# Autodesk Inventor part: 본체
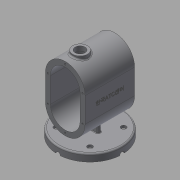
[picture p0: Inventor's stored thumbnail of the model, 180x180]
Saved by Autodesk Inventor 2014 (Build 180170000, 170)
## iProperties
Created: 2016-12
Part Number: 본체
Material: 일반
Document SubType Name: Modeling
Designer: mduedu
Density: 1 g/cm^3
Appearance: 기본값
Author: mduedu
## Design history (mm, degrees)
sketch "스케치1"
  geometry: L1 (40, -25)-(40, 25); L2 (-40, 25)-(-40, -25); L3 (-40, -25)-(40, 25); L4 (40, -25)-(-40, 25); L5 (0, 25)-(0, -25); A1 r 40 centre (0, 25) between (40, 25) and (-40, 25); A2 r 40 centre (0, -25) between (-40, -25) and (40, -25); 1 further point
  constraints: 10 end point, 4 point on circle, 3 tangent, 2 centre point, 2 midpoint, 2 parallel, 1 vertical
  dimensions: "d0" = 130 dimension on A2 A1; "d2" = 80 distance between parallel lines of L1 L2
extrude "돌출1" new body sketch "스케치1" stored distance "d3" = 100; taper "d4" = 0 deg
feature "쉘1" dims "d5" = 10
sketch "스케치2"
  geometry: L1 (-75, 65)-(-90, 65); L2 (-90, 65)-(-90, 0); L3 (-75, 0)-(-75, 65); L4 (-75, 0)-(-90, 0); 1 further point
  constraints: 8 end point, 1 horizontal, 1 horizontal alignment, 1 parallel, 1 perpendicular
  dimensions: "d6" = 90 distance from line of L2 point (0, 0); "d83" = 15 distance of L1.start L1.end; "d84" = 130 diameter of L1 L4
revolve "회전1" sketch "스케치2" stored, may be unused: angle "d85" = 90 deg
fillet "모깎기5" dims "d86" = 3
hole "구멍6" diameter "d89" = 120; stored, may be unused: countersink angle "d93" = 90 deg, drill point angle "d95" = 0 deg; dims "d87" = 10, "d88" = 10, "d90" = 6, "d91" = 4, "d92" = 2, "d94" = 10
sketch "스케치15"
  geometry: L1 (-90, -60)-(-90, 60) reference; C1 r 5 at (-90, 0); 1 further point
  constraints: 1 centre point, 1 horizontal alignment, 1 midpoint
  dimensions: "d96" = 10 diameter of C1
extrude "돌출6" cut sketch "스케치15" stored distance "d97" = 10; taper "d98" = 0 deg
sketch "스케치5"
  geometry: L1 (4, -30)-(-4, -30); L2 (-4, -30)-(-4, 30); L3 (-4, 30)-(4, 30); L4 (4, 30)-(4, -30); L5 (4, -30)-(-4, 30); L6 (-4, -30)-(4, 30); 3 further points
  constraints: 12 end point, 3 midpoint, 2 parallel, 1 coincident, 1 horizontal, 1 perpendicular
  dimensions: "d22" = 8 distance of L2.end L3.end; "d24" = 60 distance of L1.end L2.end
extrude "돌출3" join sketch "스케치5" stored distance "d25" = 80; taper "d26" = 0 deg
feature "면 기울기1" dims angle "d27" = 5 deg
sketch "스케치6"
  geometry: L1 (-18.718, -60.35)-(-20, -75); L2 (-62, -75)-(62, -75) reference; A1 r 40 centre (0, -25) between (-40, -25) and (40, -25) reference; 1 further point
  constraints: 2 end point, 1 point on circle, 1 point on line
  dimensions: "d28" = 20 horizontal distance of A1.centre L1.end; "d102" = 85 deg angle of L2 L1
feature "리브1" sketch "스케치6" dims "d30" = 1, "d31" = 8, "d32" = 0, "d33" = 0, "d34" = 1, "d35" = 1
fillet "모깎기2" dims "d36" = 3
fillet "모깎기3" dims "d37" = 1, "d38" = 1
node "작업 평면1"
sketch "스케치9"
  geometry: 1 further point
sketch "스케치7"
  geometry: L1 (40, 50)-(-40, 50) reference; C1 r 15 at (0, 20); 1 further point
  constraints: 1 centre point, 1 vertical alignment
  dimensions: "d40" = 30 diameter of C1; "d41" = 30 distance from line of C1.centre L1
extrude "돌출4" join sketch "스케치7" stored distance "d42" = 80; taper "d43" = 0 deg
hole "구멍2" diameter "d46" = 20; stored, may be unused: countersink angle "d50" = 90 deg, drill point angle "d52" = 118 deg; dims "d44" = 10, "d45" = 10, "d47" = 6, "d48" = 4, "d49" = 2, "d51" = 8
fillet "모깎기4" dims "d53" = 3
node "작업 평면2"
sketch "스케치8"
  geometry: C1 r 15 at (0, 0) reference; C2 r 15 at (0, 0); 1 further point
  constraints: 1 centre point, 1 coincident
  dimensions: "d55" = 30 diameter of C2
extrude "돌출5" cut sketch "스케치8" stored distance "d56" = 80; taper "d57" = 0 deg
chamfer "모따기1" distance "d58" = 1; stored, may be unused: second distance "d59" = 2, angle "d60" = 45 deg
sketch "스케치10"
  geometry: 2 further points
  constraints: 1 coincident, 1 other
feature "엠보싱1" sketch "스케치10" dims "d0" = 130, "d2" = 80, "d61" = 0.5, "d62" = 0
sketch "스케치11"
  geometry: 1 further point
hole "구멍3" sketch "스케치11" at (0, 60) diameter "d63" = 3.242; stored, may be unused: countersink angle "d67" = 90 deg, drill point angle "d69" = 120 deg; dims "d64" = 8.6, "d65" = 4, "d66" = 2, "d68" = 10.6
sketch "스케치12"
  geometry: 1 further point
hole "구멍5" sketch "스케치12" at (0, 60) diameter "d70" = 3.242; stored, may be unused: countersink angle "d74" = 90 deg, drill point angle "d76" = 120 deg; dims "d71" = 8.6, "d72" = 4, "d73" = 2, "d75" = 10.6
sketch "스케치16"
  geometry: L1 (0, 0)-(0, 48); L2 (0, 0)-(-33.941, 33.941); A1 r 48 centre (0, 0) between (0, 48) and (-33.941, 33.941); 2 further points
  constraints: 4 end point, 2 coincident, 2 point on circle, 1 centre point, 1 vertical
  dimensions: "d103" = 96 diameter of A1; "d104" = 45 deg angle of L1 L2
hole "구멍7" sketch "스케치16" at (-33.941, 33.941) diameter "d108" = 10; stored, may be unused: countersink angle "d112" = 90 deg, drill point angle "d114" = 118 deg; dims "d109" = 6, "d110" = 4, "d111" = 2, "d113" = 10
node "솔리드1"
pattern_circular "원형 패턴1" dims angle "d100" = 90 deg
mirror "대칭1"
pattern_linear "직사각형 패턴1"
pattern_linear "직사각형 패턴2"
pattern_circular "원형 패턴2" dims "d35" = 1, angle "d116" = 360 deg
sketch "스케치13"
  geometry: L1 (-40, 25)-(-40, -25) reference; L2 (40, -25)-(40, 25) reference; L3 (35, 25)-(35, -25); L4 (-35, -25)-(-35, 25); A1 r 40 centre (0, 25) between (40, 25) and (-40, 25) reference; A2 r 40 centre (0, -25) between (-40, -25) and (40, -25) reference; A3 r 35 centre (0, 25) between (35, 25) and (-35, 25); A4 r 35 centre (0, -25) between (-35, -25) and (35, -25); 2 further points
  constraints: 5 point on circle, 4 end point, 2 centre point, 3 other
  dimensions: "d77" = 5 distance between parallel lines of L3 L2
sketch "스케치14"
  geometry: L1 (-40, 25)-(-40, -25) reference; L2 (40, -25)-(40, 25) reference; L3 (35, 25)-(35, -25); L4 (-35, -25)-(-35, 25); A1 r 40 centre (0, 25) between (40, 25) and (-40, 25) reference; A2 r 40 centre (0, -25) between (-40, -25) and (40, -25) reference; A3 r 35 centre (0, 25) between (35, 25) and (-35, 25); A4 r 35 centre (0, -25) between (-35, -25) and (35, -25); 2 further points
  constraints: 5 point on circle, 4 end point, 2 centre point, 3 other
  dimensions: "d80" = 5 distance between parallel lines of L2 L3
